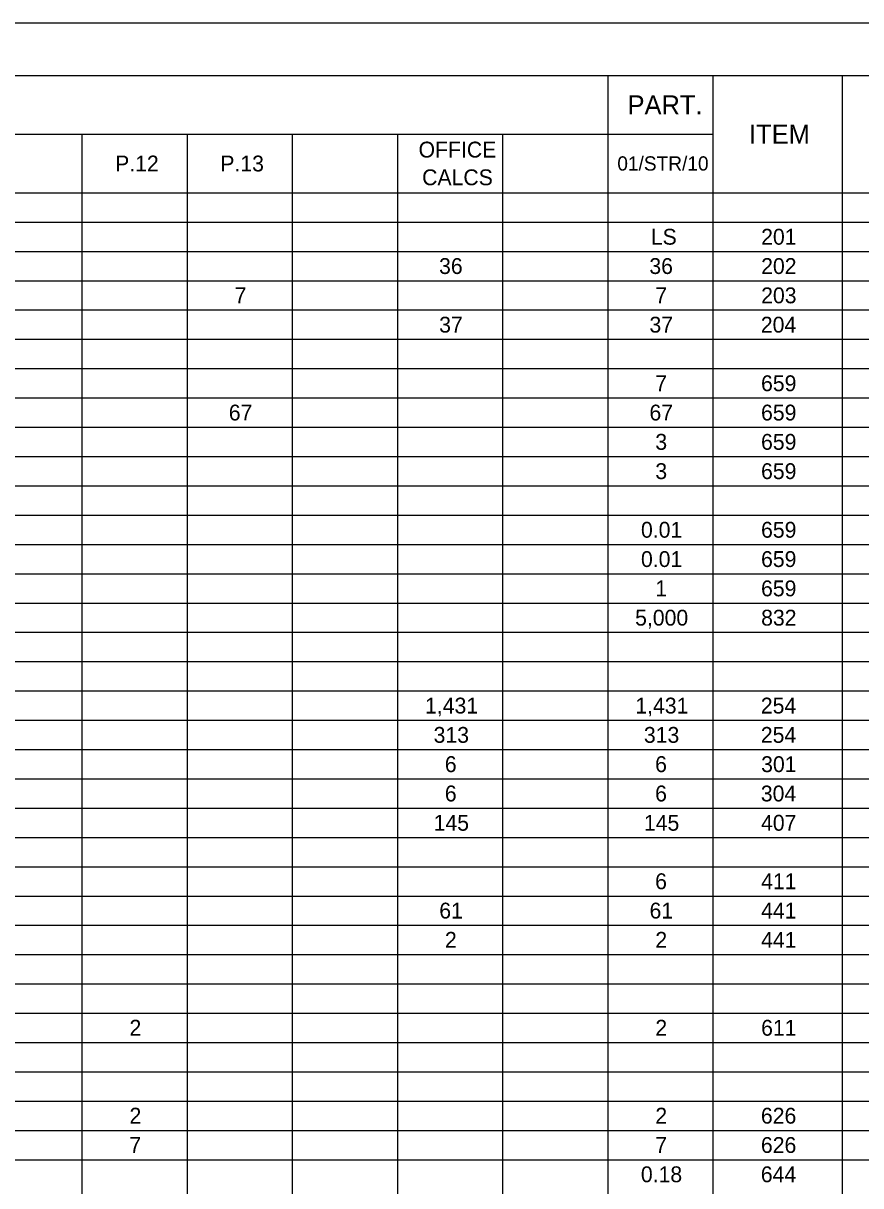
# Model space of a CAD drawing. Extents: x 0 to 34, y 0 to 22.
# Drawn here: x 8.98 to 16.98, y 10.89 to 22 of the extents above; entities that cross this region are included whole.
import ezdxf

# ---------------------------------------------------------------- set-up
doc = ezdxf.new("R2010")
doc.units = 0
for name, color, linetype in [('SH_Border', 7, 'Continuous'), ('SH_Cut_Line', 7, 'Continuous'), ('SH_Text', 7, 'Continuous')]:
    doc.layers.add(name, color=color, linetype=linetype)

msp = doc.modelspace()

# ---------------------------------------------------------------- linework, layer by layer
at = {"layer": 'SH_Border'}
msp.add_lwpolyline([(1.5, 21.5), (33.5, 21.5), (33.5, 0.5), (1.5, 0.5)], close=True, dxfattribs=at)
at = {"layer": 'SH_Cut_Line'}
msp.add_lwpolyline([(0, 0), (34, 0), (34, 22), (0, 22)], close=True, dxfattribs=at)
at = {"layer": 'SH_Text'}
for p, q in [((1.5, 21.5), (32.002, 21.5)), ((14.561, 21.5), (14.561, 0.501)), ((15.565, 21.5), (15.565, 0.501)), ((16.801, 21.5), (16.801, 0.501)), ((1.5, 20.94), (15.565, 20.94)), ((9.537, 20.94), (9.537, 0.501)), ((10.542, 20.94), (10.542, 0.501)), ((11.547, 20.94), (11.547, 0.501)), ((12.551, 20.94), (12.551, 0.501)), ((13.556, 20.94), (13.556, 0.501)), ((1.5, 20.38), (32.002, 20.38)), ((1.5, 20.1), (32.002, 20.1)), ((1.5, 19.82), (32.002, 19.82)), ((1.5, 19.54), (32.002, 19.54)), ((1.5, 19.26), (32.002, 19.26)), ((1.5, 18.98), (32.002, 18.98)), ((1.5, 18.7), (32.002, 18.7)), ((1.5, 18.42), (32.002, 18.42)), ((1.5, 18.14), (32.002, 18.14)), ((1.5, 17.86), (32.002, 17.86)), ((1.5, 17.58), (32.002, 17.58)), ((1.5, 17.3), (32.002, 17.3)), ((1.5, 17.02), (32.002, 17.02)), ((1.5, 16.74), (32.002, 16.74)), ((1.5, 16.46), (32.002, 16.46)), ((1.5, 16.18), (32.002, 16.18)), ((1.5, 15.9), (32.002, 15.9)), ((1.5, 15.62), (32.002, 15.62)), ((1.5, 15.34), (32.002, 15.34)), ((1.5, 15.06), (32.002, 15.06)), ((1.5, 14.78), (32.002, 14.78)), ((1.5, 14.5), (32.002, 14.5)), ((1.5, 14.22), (32.002, 14.22)), ((1.5, 13.94), (32.002, 13.94)), ((1.5, 13.66), (32.002, 13.66)), ((1.5, 13.38), (32.002, 13.38)), ((1.5, 13.1), (32.002, 13.1)), ((1.5, 12.82), (32.002, 12.82)), ((1.5, 12.54), (32.002, 12.54)), ((1.5, 12.26), (32.002, 12.26)), ((1.5, 11.98), (32.002, 11.98)), ((1.5, 11.7), (32.002, 11.7)), ((1.5, 11.42), (32.002, 11.42)), ((1.5, 11.14), (32.002, 11.14))]:
    msp.add_line(p, q, dxfattribs=at)

# ---------------------------------------------------------------- texts
for s, height, p in [('PART.', 0.1818, (14.75, 21.129)), ('ITEM', 0.1818, (15.911, 20.849)), ('OFFICE', 0.1515, (12.753, 20.717)), ('P.12', 0.1515, (9.854, 20.584)), ('P.13', 0.1515, (10.859, 20.584)), ('01/STR/10', 0.1364, (14.652, 20.592)), ('CALCS', 0.1515, (12.787, 20.452)), ('LS', 0.1515, (14.972, 19.884)), ('201', 0.1515, (16.026, 19.884)), ('36', 0.1515, (12.949, 19.604)), ('36', 0.1515, (14.958, 19.604)), ('202', 0.1515, (16.026, 19.604)), ('7', 0.152, (10.995, 19.324)), ('7', 0.152, (15.014, 19.324)), ('203', 0.1515, (16.026, 19.324)), ('37', 0.1515, (12.95, 19.044)), ('37', 0.1515, (14.959, 19.044)), ('204', 0.1515, (16.023, 19.044)), ('7', 0.152, (15.014, 18.484)), ('659', 0.1515, (16.025, 18.484)), ('67', 0.1515, (10.94, 18.204)), ('67', 0.1515, (14.959, 18.204)), ('659', 0.1515, (16.025, 18.204)), ('3', 0.152, (15.015, 17.924)), ('659', 0.1515, (16.025, 17.924)), ('3', 0.152, (15.015, 17.644)), ('659', 0.1515, (16.025, 17.644)), ('0.01', 0.1515, (14.878, 17.084)), ('659', 0.1515, (16.025, 17.084)), ('0.01', 0.1515, (14.878, 16.804)), ('659', 0.1515, (16.025, 16.804)), ('1', 0.152, (15.014, 16.524)), ('659', 0.1515, (16.025, 16.524)), ('5,000', 0.1515, (14.822, 16.244)), ('832', 0.1515, (16.026, 16.244)), ('1,431', 0.1515, (12.815, 15.404)), ('1,431', 0.1515, (14.824, 15.404)), ('254', 0.1515, (16.023, 15.404)), ('313', 0.1515, (12.897, 15.124)), ('313', 0.1515, (14.906, 15.124)), ('254', 0.1515, (16.023, 15.124)), ('6', 0.152, (13.004, 14.844)), ('6', 0.152, (15.013, 14.844)), ('301', 0.1515, (16.026, 14.844)), ('6', 0.152, (13.004, 14.564)), ('6', 0.152, (15.013, 14.564)), ('304', 0.1515, (16.023, 14.564)), ('145', 0.1515, (12.897, 14.284)), ('145', 0.1515, (14.906, 14.284)), ('407', 0.1515, (16.025, 14.284)), ('6', 0.152, (15.013, 13.725)), ('411', 0.1515, (16.026, 13.725)), ('61', 0.1515, (12.951, 13.445)), ('61', 0.1515, (14.96, 13.445)), ('441', 0.1515, (16.026, 13.445)), ('2', 0.152, (13.005, 13.165)), ('2', 0.152, (15.015, 13.165)), ('441', 0.1515, (16.026, 13.165)), ('2', 0.152, (9.991, 12.325)), ('2', 0.152, (15.015, 12.325)), ('611', 0.1515, (16.026, 12.325)), ('2', 0.152, (9.991, 11.485)), ('2', 0.152, (15.015, 11.485)), ('626', 0.1515, (16.024, 11.485)), ('7', 0.152, (9.99, 11.205)), ('7', 0.152, (15.014, 11.205)), ('626', 0.1515, (16.024, 11.205)), ('0.18', 0.1515, (14.877, 10.925)), ('644', 0.1515, (16.023, 10.925))]:
    msp.add_text(s, height=height, dxfattribs=at).set_placement(p)

doc.saveas('drawing.dxf')
